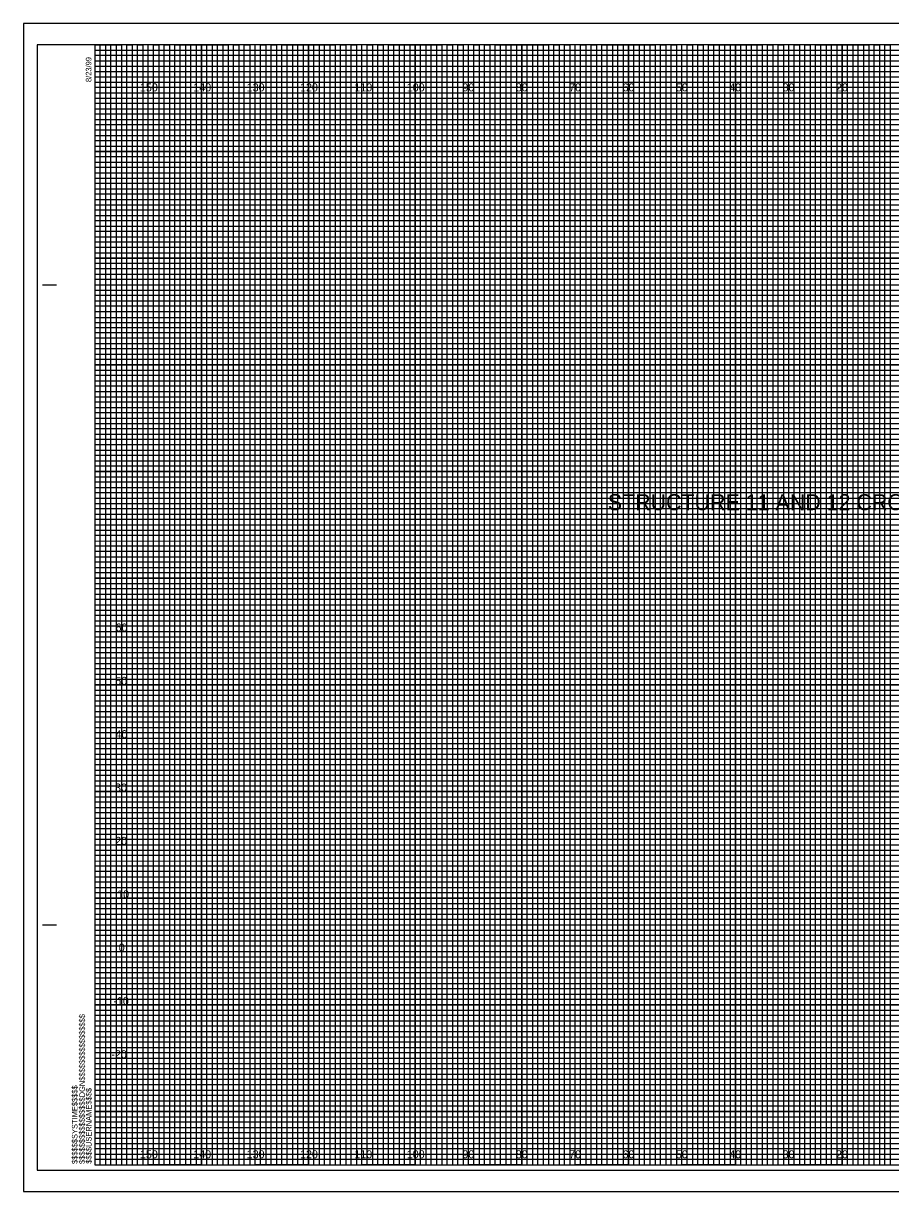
# Model space of a CAD drawing. Extents: x -13 to 886, y -5 to 434.
# Drawn here: x -13.4 to 149.1, y -5 to 214 of the extents above; entities that cross this region are included whole.
import ezdxf

# ---------------------------------------------------------------- set-up
doc = ezdxf.new("R2010")
doc.units = 0
for name, color, linetype in [('Prop Road Sect_ Boring - Header Labels from Geopak', 7, 'Continuous'), ('Prop XS Elevation Labels', 7, 'Continuous'), ('Prop XS Offset Labels', 7, 'Continuous'), ('Sheet Cross Section CELL', 7, 'Continuous'), ('Sheet Cross Section Grid Major CELL', 7, 'Continuous'), ('Sheet Cross Section Grid Middle CELL', 7, 'Continuous'), ('Sheet Cross Section Grid Minor 1 CELL', 7, 'Continuous'), ('Sheet Cross Section Grid Minor 2 CELL', 7, 'Continuous'), ('Sheet Cutting Line CELL', 7, 'Continuous'), ('Sheet DOT Grid CELL', 7, 'Continuous'), ('Sheet Plot Border Inside CELL', 7, 'Continuous'), ('Sheet Plot Border Outside CELL', 7, 'Continuous')]:
    doc.layers.add(name, color=color, linetype=linetype)

msp = doc.modelspace()

# ---------------------------------------------------------------- linework, layer by layer
at = {"layer": 'Sheet Cross Section CELL'}
for p, q in [((-9.8, 165), (-7.3, 165)), ((-9.7, 165), (-7.2, 165)), ((-9.8, 45), (-7.3, 45)), ((-9.7, 45), (-7.2, 45)), ((0, 0), (0, 0)), ((0, 0), (0, 0)), ((0, 0), (0, 0)), ((0, 0), (0, 0)), ((0, 0), (0, 0)), ((0, 0), (0, 0)), ((0, 0), (0, 0))]:
    msp.add_line(p, q, dxfattribs=at)
msp.add_lwpolyline([(320, 210), (0, 210), (0, 0), (320, 0)], close=True, dxfattribs=at)
at = {"layer": 'Sheet Cross Section Grid Major CELL'}
for p, q in [((10, 210), (0, 210)), ((10, 0), (10, 210)), ((30, 210), (20, 210)), ((20, 210), (20, 0)), ((30, 0), (30, 210)), ((50, 210), (40, 210)), ((40, 210), (40, 0)), ((50, 0), (50, 210)), ((70, 210), (60, 210)), ((60, 210), (60, 0)), ((70, 0), (70, 210)), ((90, 210), (80, 210)), ((80, 210), (80, 0)), ((90, 0), (90, 210)), ((110, 210), (100, 210)), ((100, 210), (100, 0)), ((110, 0), (110, 210)), ((130, 210), (120, 210)), ((120, 210), (120, 0)), ((130, 0), (130, 210)), ((150, 210), (140, 210)), ((140, 210), (140, 0)), ((20, 0), (10, 0)), ((40, 0), (30, 0)), ((60, 0), (50, 0)), ((80, 0), (70, 0)), ((100, 0), (90, 0)), ((120, 0), (110, 0)), ((140, 0), (130, 0))]:
    msp.add_line(p, q, dxfattribs=at)
for points in [[(0, 200), (320, 200), (320, 190), (0, 190)], [(0, 180), (320, 180), (320, 170), (0, 170)], [(0, 160), (320, 160), (320, 150), (0, 150)], [(0, 140), (320, 140), (320, 130), (0, 130)], [(0, 120), (320, 120), (320, 110), (0, 110)], [(0, 100), (320, 100), (320, 90), (0, 90)], [(0, 80), (320, 80), (320, 70), (0, 70)], [(0, 60), (320, 60), (320, 50), (0, 50)], [(0, 40), (320, 40), (320, 30), (0, 30)], [(0, 20), (320, 20), (320, 10), (0, 10)]]:
    msp.add_lwpolyline(points, dxfattribs=at)
at = {"layer": 'Sheet Cross Section Grid Middle CELL'}
for points in [[(0, 210), (5, 210), (5, 0), (15, 0), (15, 210), (25, 210), (25, 0), (35, 0), (35, 210), (45, 210), (45, 0), (55, 0), (55, 210), (65, 210), (65, 0), (75, 0), (75, 210), (85, 210), (85, 0), (95, 0), (95, 210), (105, 210), (105, 0), (115, 0), (115, 210), (125, 210), (125, 0), (135, 0), (135, 210), (145, 210), (145, 0), (155, 0)], [(0, 205), (275, 205)], [(0, 185), (320, 185), (320, 195), (0, 195)], [(0, 165), (320, 165), (320, 175), (0, 175)], [(0, 145), (320, 145), (320, 155), (0, 155)], [(0, 125), (320, 125), (320, 135), (0, 135)], [(0, 105), (320, 105), (320, 115), (0, 115)], [(0, 85), (320, 85), (320, 95), (0, 95)], [(0, 65), (320, 65), (320, 75), (0, 75)], [(0, 45), (320, 45), (320, 55), (0, 55)], [(0, 25), (320, 25), (320, 35), (0, 35)], [(0, 5), (320, 5), (320, 15), (0, 15)]]:
    msp.add_lwpolyline(points, dxfattribs=at)
at = {"layer": 'Sheet Cross Section Grid Minor 1 CELL'}
for p, q in [((0, 209), (260, 209)), ((260, 207.98), (0, 207.98)), ((0, 207.98), (0, 207)), ((0, 207), (260, 207)), ((260, 205.89), (0, 205.89)), ((0, 205.89), (0, 204)), ((0, 204), (320, 204))]:
    msp.add_line(p, q, dxfattribs=at)
for points in [[(0, 203), (270, 203), (320, 203), (320, 202), (0, 202)], [(0, 201), (320, 201), (320, 199), (0, 199)], [(0, 198), (320, 198), (320, 197), (0, 196.98)], [(0, 196), (320, 196), (320, 194), (0, 194)], [(0, 193), (320, 193), (320, 192), (0, 192)], [(0, 191), (320, 191), (320, 189), (0, 189)], [(0, 188), (320, 188), (320, 187), (0, 187)], [(0, 186), (320, 186), (320, 184), (0, 184)], [(0, 183), (320, 183), (320, 182), (0, 182)], [(0, 181), (320, 181), (320, 179), (0, 179)], [(0, 178), (320, 178), (320, 177), (0, 177)], [(0, 176), (320, 176), (320, 173.95), (320, 173), (320, 172), (0, 172)], [(0, 174), (320, 174), (320, 173), (0, 173)], [(0, 171), (320, 171), (320, 169), (0, 169.03)], [(0, 169.03), (320, 169), (320, 168), (0, 168)], [(0, 167), (320, 167), (320, 166), (0, 166)], [(0, 164), (320, 164), (320, 163), (0, 163)], [(0, 162), (320, 162), (320, 161), (0, 161)], [(-0.07, 158.89), (320, 158.89), (320, 157.88), (-0.07, 157.88)], [(0, 157), (320, 157), (320, 156), (0, 156)], [(0, 154), (320, 154), (320, 153), (0, 153)], [(0, 152), (320, 152), (320, 151), (0, 151)], [(0, 149), (320, 149), (320, 148), (0, 148)], [(0, 147), (320, 147), (320, 146), (0, 146)], [(0, 144), (320, 144), (320, 143), (0, 143)], [(0, 142), (320, 142), (320, 141), (0, 141)], [(0, 139), (320, 139), (319.99, 137.98), (0, 138)], [(0, 137), (320, 137), (320, 136), (0, 136)], [(0, 134), (320, 134), (320, 133), (0, 133)], [(0, 132), (320, 132), (320, 131), (0, 131)], [(0, 129), (320, 129), (320, 128), (0, 128)], [(0, 127), (320, 127), (320, 126), (0, 126)], [(0, 124), (320, 124), (320, 123), (0, 123)], [(0, 122), (320, 122), (320, 121), (0, 121)], [(0, 119), (320, 119), (320, 118), (0, 118)], [(0, 116.99), (320.07, 116.91), (320, 116), (0, 116)], [(0, 114), (320, 114), (320, 113), (0, 113)], [(0, 112), (320, 112), (320, 111), (0, 111)], [(0, 109), (320, 109), (320, 108), (0, 108)], [(0, 107), (320, 107), (320, 106), (0, 106)], [(0, 104), (320, 104), (320, 103), (0, 103)], [(0, 102), (320, 102), (320, 101), (0, 101)], [(0, 99), (320, 99), (320, 98), (0, 98)], [(0, 97), (320, 97), (320, 96), (0, 96)], [(0, 94), (320, 94), (320, 93), (0, 93)], [(0, 92), (320, 92), (320, 91), (0, 91)], [(0, 89), (320, 89), (320, 88), (0, 88)], [(0, 87), (320, 87), (320, 86), (0, 86)], [(0, 84), (320, 84), (320, 83), (0, 83)], [(0, 82), (320, 82), (320, 81), (0, 81)], [(0, 79), (320, 79), (319.99, 77.98), (0, 78)], [(0, 77), (320, 77), (320, 76), (0, 76)], [(0, 74), (320, 74), (320, 73), (0, 73)], [(0, 72), (320, 72), (320, 71), (0, 71)], [(0, 69), (320, 69), (320, 68), (0, 68)], [(0, 67), (320, 67), (320, 66), (0, 66)], [(0, 64), (320, 64), (320, 63), (0, 63)], [(0, 62), (320, 62), (320, 61), (0, 61)], [(0, 59), (320, 59), (320, 58), (0, 58)], [(0, 56.99), (320.07, 56.91), (320, 56), (0, 56)], [(0, 54), (320, 54), (320, 53), (0, 53)], [(0, 52), (320, 52), (320, 51), (0, 51)], [(0, 49), (320, 49), (320, 48), (0, 48)], [(0, 47), (320, 47), (320, 46), (0, 46)], [(0, 44), (320, 44), (320, 43), (0, 43)], [(0, 42), (320, 42), (320, 41), (0, 41)], [(0, 39), (320, 39), (320, 38), (0, 38)], [(0, 37), (320, 37), (320, 36), (0, 36)], [(0, 34), (320, 34), (320, 33), (0, 33)], [(0, 32), (320, 32), (320, 31), (0, 31)], [(0, 29), (320, 29), (320, 28), (0, 28)], [(0, 27), (320, 27), (320, 26), (0, 26)], [(0, 24), (320, 24), (320, 23), (0, 23)], [(0, 22), (320, 22), (320, 21), (0, 21)], [(0, 19), (320, 19), (320, 18), (0, 18)], [(0, 17), (320, 17), (320, 16), (0, 16)], [(0, 14), (320, 14), (320, 13), (0, 13)], [(0, 12), (320, 12), (320, 11), (0, 11)], [(0, 9), (320, 9), (320, 8), (0, 8)], [(0, 7), (320, 7), (320, 6), (0, 6)], [(0, 4), (320, 4), (320, 3), (0, 3)], [(0, 2), (320, 2), (320, 1), (0, 1)]]:
    msp.add_lwpolyline(points, dxfattribs=at)
at = {"layer": 'Sheet Cross Section Grid Minor 2 CELL'}
for points in [[(0, 0), (1, 0), (1, 210), (2, 210), (2, 0)], [(2, 0), (3, 0), (3, 210), (4, 210), (4, 0)], [(5, 0), (6, 0), (6, 210), (7, 210), (7, 0)], [(7, 0), (8, 0), (8, 210), (9, 210), (9, 0)], [(10, 0), (11, 0), (11, 210), (12, 210), (12, 0)], [(12, 0), (13, 0), (13, 210), (14, 210), (14, 0)], [(15, 0), (16, 0), (16, 210), (17, 210), (17, 0)], [(17, 0), (18, 0), (18, 210), (19, 210), (19, 0)], [(20, 0), (21, 0), (21, 210), (22, 210), (22, 0)], [(22, 0), (23, 0), (23, 210), (24, 210), (24, 0)], [(25, 0), (26, 0), (26, 210), (27, 210), (27, 0)], [(27, 0), (28, 0), (28, 210), (29, 210), (29, 0)], [(30, 0), (31, 0), (31, 210), (32, 210), (32, 0)], [(32, 0), (33, 0), (33, 210), (34, 210), (34, 0)], [(35, 0), (36, 0), (36, 210), (37, 210), (37, 0)], [(37, 0), (38, 0), (38, 210), (39, 210), (39, 0)], [(40, 0), (41, 0), (41, 210), (42, 210), (42, 0)], [(42, 0), (43, 0), (43, 210), (44, 210), (44, 0)], [(45, 0), (46, 0), (46, 210), (47, 210), (47, 0)], [(47, 0), (48, 0), (48, 210), (49, 210), (49, 0)], [(50, 0), (51, 0), (51, 210), (52, 210), (52, 0)], [(52, 0), (53, 0), (53, 210), (54, 210), (54, 0)], [(55, 0), (56, 0), (56, 210), (57, 210), (57, 0)], [(57, 0), (58, 0), (58, 210), (59, 210), (59, 0)], [(60, 0), (61, 0), (61, 210), (62, 210), (62, 0)], [(62, 0), (63, 0), (63, 210), (64, 210), (64, 0)], [(65, 0), (66, 0), (66, 210), (67, 210), (67, 0)], [(67, 0), (68, 0), (68, 210), (69, 210), (69, 0)], [(70, 0), (71, 0), (71, 210), (72, 210), (72, 0)], [(72, 0), (73, 0), (73, 210), (74, 210), (74, 0)], [(75, 0), (76, 0), (76, 210), (77, 210), (77, 0)], [(77, 0), (78, 0), (78, 210), (79, 210), (79, 0)], [(80, 0), (81, 0), (81, 210), (82, 210), (82, 0)], [(82, 0), (83, 0), (83, 210), (84, 210), (84, 0)], [(85, 0), (86, 0), (86, 210), (87, 210), (87, 0)], [(87, 0), (88, 0), (88, 210), (89, 210), (89, 0)], [(90, 0), (91, 0), (91, 210), (92, 210), (92, 0)], [(92, 0), (93, 0), (93, 210), (94, 210), (94, 0)], [(95, 0), (96, 0), (96, 210), (97, 210), (97, 0)], [(97, 0), (98, 0), (98, 210), (99, 210), (99, 0)], [(100, 0), (101, 0), (101, 210), (102, 210), (102, 0)], [(102, 0), (103, 0), (103, 210), (104, 210), (104, 0)], [(105, 0), (106, 0), (106, 210), (107, 210), (107, 0)], [(107, 0), (108, 0), (108, 210), (109, 210), (109, 0)], [(110, 0), (111, 0), (111, 210), (112, 210), (112, 0)], [(112, 0), (113, 0), (113, 210), (114, 210), (114, 0)], [(115, 0), (116, 0), (116, 210), (117, 210), (117, 0)], [(117, 0), (118, 0), (118, 210), (119, 210), (119, 0)], [(120, 0), (121, 0), (121, 210), (122, 210), (122, 0)], [(122, 0), (123, 0), (123, 210), (124, 210), (124, 0)], [(125, 0), (126, 0), (126, 210), (127, 210), (127, 0)], [(127, 0), (128, 0), (128, 210), (129, 210), (129, 0)], [(130, 0), (131, 0), (131, 210), (132, 210), (132, 0)], [(132, 0), (133, 0), (133, 210), (134, 210), (134, 0)], [(135, 0), (136, 0), (136, 210), (137, 210), (137, 0)], [(137, 0), (138, 0), (138, 210), (139, 210), (139, 0)], [(140, 0), (141, 0), (141, 210), (142, 210), (142, 0)], [(142, 0), (143, 0), (143, 210), (144, 210), (144, 0)], [(145, 0), (146, 0), (146, 210), (147, 210), (147, 0)], [(147, 0), (148, 0), (148, 210), (149, 210), (149, 0)]]:
    msp.add_lwpolyline(points, dxfattribs=at)
at = {"layer": 'Sheet Cutting Line CELL'}
for p, q in [((323.3, 214), (-13.4, 214)), ((-13.4, 214), (-13.4, -5)), ((-13.4, -5), (323.3, -5))]:
    msp.add_line(p, q, dxfattribs=at)
at = {"layer": 'Sheet DOT Grid CELL'}
for p, q in [((10, 0), (10, 210)), ((20, 0), (20, 210)), ((30, 0), (30, 210)), ((40, 0), (40, 210)), ((50, 0), (50, 210)), ((60, 0), (60, 210)), ((70, 0), (70, 210)), ((80, 0), (80, 210)), ((90, 0), (90, 210)), ((100, 0), (100, 210)), ((110, 0), (110, 210)), ((120, 0), (120, 210)), ((130, 0), (130, 210)), ((140, 0), (140, 210)), ((0, 200), (320, 200)), ((0, 190), (320, 190)), ((0, 180), (320, 180)), ((0, 170), (320, 170)), ((0, 160), (320, 160)), ((0, 150), (320, 150)), ((0, 140), (320, 140)), ((0, 130), (320, 130)), ((0, 120), (320, 120)), ((0, 110), (320, 110)), ((0, 100), (320, 100)), ((0, 90), (320, 90)), ((0, 80), (320, 80)), ((0, 70), (320, 70)), ((0, 60), (320, 60)), ((0, 50), (320, 50)), ((0, 40), (320, 40)), ((0, 30), (320, 30)), ((0, 20), (320, 20)), ((0, 10), (320, 10))]:
    msp.add_line(p, q, dxfattribs=at)
at = {"layer": 'Sheet Plot Border Inside CELL'}
msp.add_lwpolyline([(-10.8, -1), (322.4, -1), (322.4, 210), (-10.8, 210)], close=True, dxfattribs=at)
at = {"layer": 'Sheet Plot Border Outside CELL'}
msp.add_lwpolyline([(-13.4, -5), (323.3, -5), (323.3, 214), (-13.4, 214)], close=True, dxfattribs=at)

# ---------------------------------------------------------------- texts
at = {"layer": 'Prop Road Sect_ Boring - Header Labels from Geopak'}
msp.add_text('STRUCTURE 11 AND 12 CROSS-SECTION THROUGH END BENT 1', height=3, dxfattribs=at).set_placement((96.1, 122.74))
at = {"layer": 'Prop XS Elevation Labels'}
for s, p in [('60', (3.87, 100)), ('50', (3.82, 90)), ('40', (3.87, 80)), ('30', (3.78, 70)), ('20', (3.8, 60)), ('10', (4.17, 50)), ('0', (4.47, 40)), ('-10', (3.46, 30)), ('-20', (3.09, 20))]:
    msp.add_text(s, height=1.5, dxfattribs=at).set_placement(p)
at = {"layer": 'Prop XS Offset Labels'}
for s, p in [('150', (8.44, 201.25)), ('140', (18.44, 201.25)), ('130', (28.44, 201.25)), ('120', (38.44, 201.25)), ('110', (48.62, 201.25)), ('100', (58.44, 201.25)), ('90', (68.86, 201.25)), ('80', (78.86, 201.25)), ('70', (88.86, 201.25)), ('60', (98.86, 201.25)), ('50', (108.86, 201.25)), ('40', (118.86, 201.25)), ('30', (128.86, 201.25)), ('20', (138.86, 201.25)), ('150', (8.44, 1.25)), ('140', (18.44, 1.25)), ('130', (28.44, 1.25)), ('120', (38.44, 1.25)), ('110', (48.62, 1.25)), ('100', (58.44, 1.25)), ('90', (68.86, 1.25)), ('80', (78.86, 1.25)), ('70', (88.86, 1.25)), ('60', (98.86, 1.25)), ('50', (108.86, 1.25)), ('40', (118.86, 1.25)), ('30', (128.86, 1.25)), ('20', (138.86, 1.25))]:
    msp.add_text(s, height=1.5, dxfattribs=at).set_placement(p)
at = {"layer": 'Sheet Cross Section CELL'}
for s, p in [('8/23/99', (-0.65, 203)), ('$$$$$$$$$$$$$$$$DGN$$$$$$$$$$$$$$$$', (-1.88, 0.18)), ('$$$$$$SYSTIME$$$$$', (-3.26, 0.18)), ('$$$$USERNAME$$$$', (-0.62, 0.23))]:
    msp.add_text(s, height=1.05, rotation=90, dxfattribs=at).set_placement(p)

doc.saveas('drawing.dxf')
